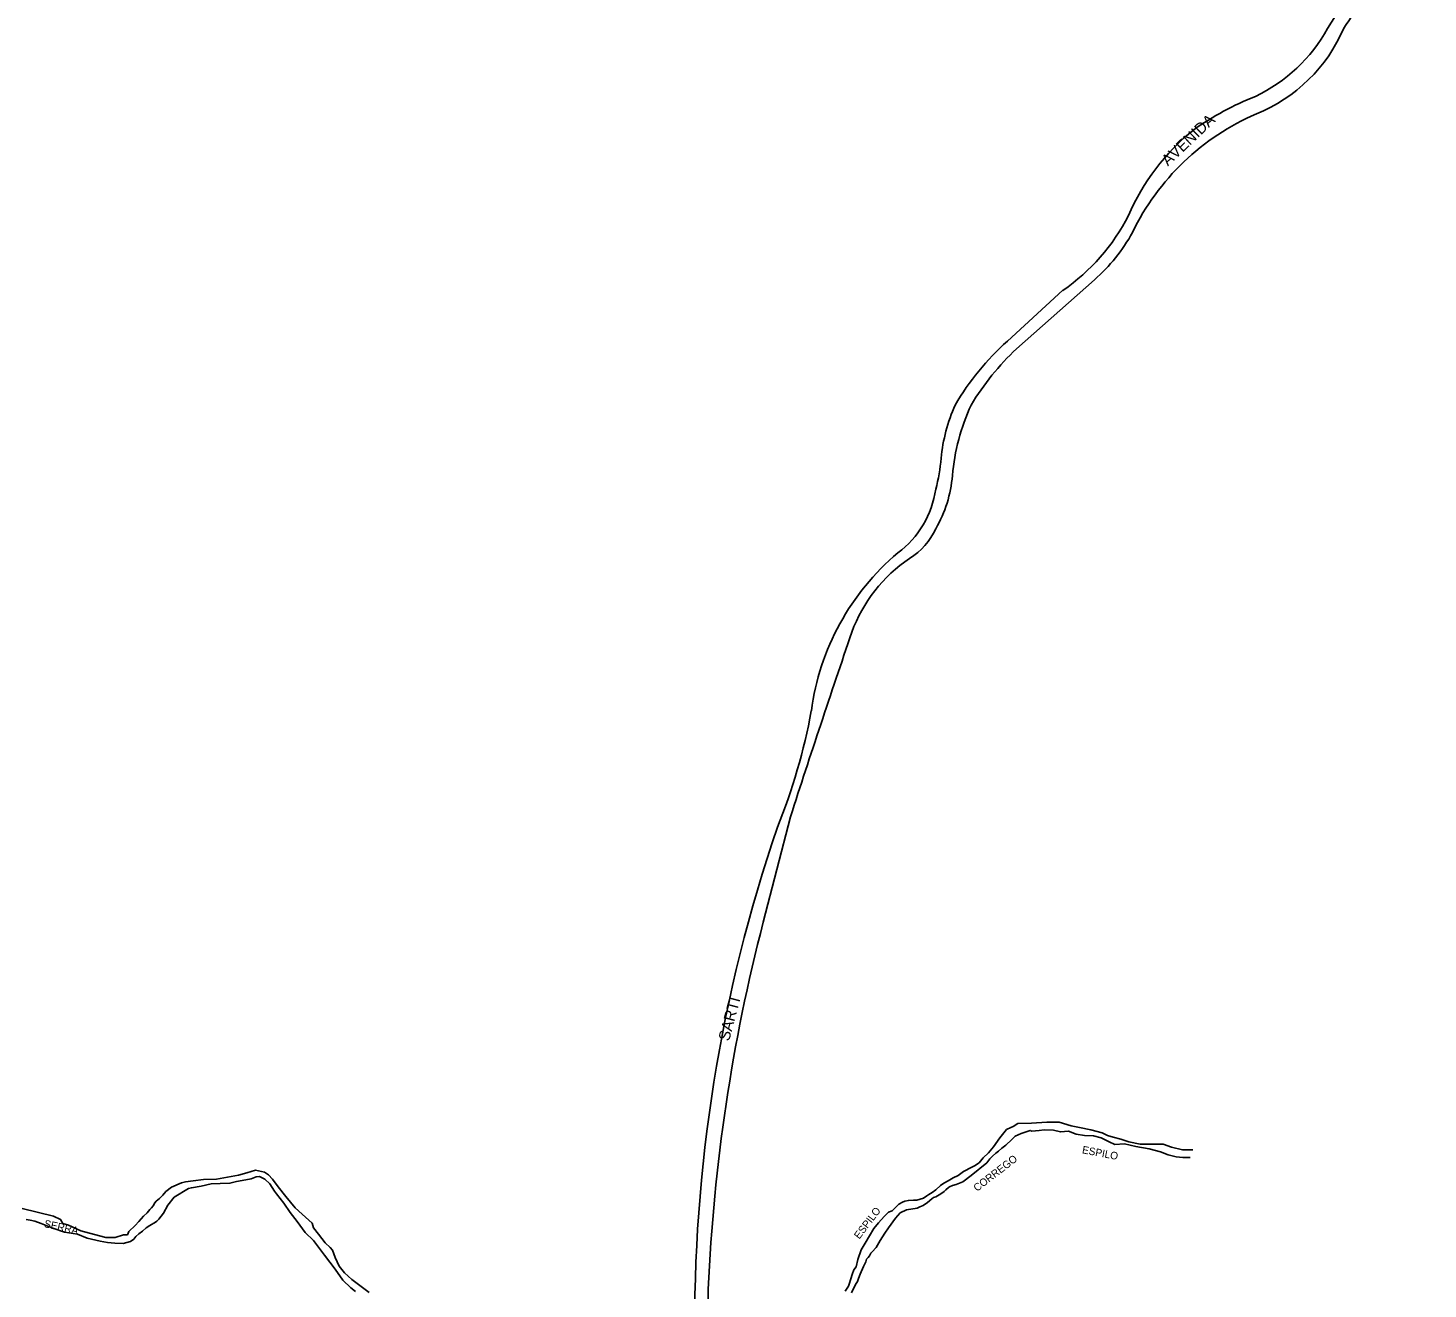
# Model space of a CAD drawing. Extents: x 325709 to 364434, y 7573432 to 7597073.
# Drawn here: x 344398 to 345143, y 7589031 to 7589703 of the extents above; entities that cross this region are included whole.
import ezdxf

# ---------------------------------------------------------------- set-up
doc = ezdxf.new("R2010")
doc.units = 0
for name, color, linetype in [('EDIFIDENTIF', 7, 'Continuous'), ('EDIFOBRAEXIS', 7, 'Continuous'), ('LOGRADOURO', 7, 'Continuous'), ('LOGRADOURO_TEXTO', 7, 'Continuous')]:
    doc.layers.add(name, color=color, linetype=linetype)

msp = doc.modelspace()

# ---------------------------------------------------------------- linework, layer by layer
at = {"layer": 'EDIFOBRAEXIS'}
for points in [[(344881.39, 7589084.09), (344883.94, 7589086.39), (344885.69, 7589087.77), (344888.03, 7589088.91), (344890.73, 7589090.47), (344893.33, 7589091.83), (344896.23, 7589093.83), (344900.67, 7589096.23), (344901.97, 7589097.01), (344904.54, 7589098.6), (344906.63, 7589101.19), (344909.46, 7589103.8), (344912.1, 7589106.96), (344915.5, 7589111.91), (344919.04, 7589116.19), (344921.29, 7589117.4), (344922.66, 7589117.88), (344925.18, 7589119.37), (344932.38, 7589119.6), (344940.59, 7589120.12), (344947.05, 7589120.15), (344953.5, 7589118.22), (344957.99, 7589117.31), (344963.94, 7589116.17), (344970.03, 7589114.45), (344972.75, 7589113.11), (344975.79, 7589112.26), (344979.83, 7589111.03), (344984.25, 7589109.61), (344990.27, 7589108.42), (345002.47, 7589108.42), (345006.96, 7589106.81), (345012.75, 7589105.44), (345018.22, 7589105.39)], [(344881.39, 7589080.43), (344883.25, 7589081.53), (344885.11, 7589082.69), (344885.87, 7589083.27), (344886.77, 7589084.14), (344888.12, 7589085.4), (344888.78, 7589085.8), (344890.38, 7589086.46), (344892.34, 7589086.98), (344895.88, 7589088.34), (344900.24, 7589091.73), (344908.58, 7589098.59), (344910.24, 7589100.59), (344911.69, 7589101.98), (344913.48, 7589103.6), (344914.86, 7589104.79), (344916.54, 7589106.31), (344918.71, 7589107.96), (344921.9, 7589110.94), (344923.63, 7589112.66), (344926.87, 7589114.05), (344931.73, 7589115.76), (344932.62, 7589115.33), (344936.53, 7589115.79), (344939.15, 7589116.04), (344944.13, 7589115.89), (344947.77, 7589114.99), (344952.14, 7589115.38), (344956.12, 7589113.74), (344960.62, 7589113.08), (344965.37, 7589112.81), (344969.46, 7589111.8), (344973.65, 7589109.73), (344976.8, 7589108.22), (344981.86, 7589108.65), (344987.95, 7589107.13), (344994.94, 7589106.01), (345001.08, 7589104.29), (345005.04, 7589102.77), (345009.28, 7589101.76), (345012.92, 7589101.34), (345016.78, 7589101.33)], [(344395.31, 7589074.17), (344412, 7589070.07), (344415.71, 7589068.3), (344416.83, 7589066.25), (344419.88, 7589065.3), (344426.41, 7589062.35), (344433.75, 7589060.45), (344439.85, 7589058.72), (344444.7, 7589058.86), (344449.19, 7589060.22), (344451.24, 7589060.23), (344452.02, 7589062.03), (344455.36, 7589065.14), (344457.26, 7589067.36), (344459.84, 7589070.13), (344461.73, 7589071.94), (344463.12, 7589073.75), (344464.01, 7589074.56), (344465.05, 7589075.56), (344465.9, 7589077.26), (344466.64, 7589078.18), (344468.26, 7589079.55), (344470.1, 7589081.23), (344471.77, 7589083.27), (344474.68, 7589085.62), (344480.11, 7589087.92), (344482.11, 7589088.33), (344486.24, 7589088.98), (344491.8, 7589089.71), (344498.63, 7589089.84), (344510.32, 7589092.03), (344514.73, 7589093.19), (344519.37, 7589094.53), (344524.27, 7589093.55), (344526.26, 7589092.12), (344528.55, 7589089.84), (344531.56, 7589085.81), (344535.51, 7589080.62), (344540.51, 7589074.65), (344544.2, 7589071.24), (344549.57, 7589066.36), (344550.29, 7589063.87), (344552.94, 7589060.56), (344556.46, 7589055.93), (344559.21, 7589053.52), (344560.38, 7589052.11), (344561.77, 7589048.18), (344563.99, 7589043.54), (344566.84, 7589040.05), (344570.61, 7589036.43), (344579.95, 7589029.56)], [(344397.36, 7589068.34), (344399.44, 7589067.97), (344402.08, 7589067.44), (344405.41, 7589066.16), (344411.56, 7589063.8), (344417.74, 7589061.64), (344424.74, 7589060.54), (344429.93, 7589058.48), (344436.79, 7589056.75), (344440.7, 7589056.16), (344444.56, 7589055.69), (344449.05, 7589055.55), (344452.93, 7589056.68), (344454.65, 7589057.8), (344455.81, 7589059.33), (344457.33, 7589060.71), (344459.28, 7589062.16), (344461.26, 7589063.84), (344463.28, 7589065.22), (344466.17, 7589066.96), (344466.95, 7589067.49), (344467.96, 7589068.49), (344470.42, 7589071.69), (344472.74, 7589075.91), (344476.1, 7589080.19), (344483.77, 7589084.94), (344485.37, 7589085.25), (344490.59, 7589086.15), (344495.77, 7589087.26), (344500.66, 7589087.43), (344505.84, 7589087.68), (344509.39, 7589088.63), (344514.26, 7589089.41), (344517.13, 7589090), (344519.87, 7589091), (344521.57, 7589091.16), (344524.41, 7589089.82), (344527.04, 7589087.37), (344529.49, 7589083.5), (344530.63, 7589082.08), (344534.58, 7589077.07), (344537.8, 7589072.08), (344541.52, 7589067.32), (344545.81, 7589061.45), (344550.24, 7589057.1), (344556.1, 7589049.4), (344561.79, 7589041.83), (344565.89, 7589036.04), (344570.17, 7589031.96), (344572.72, 7589030.07)], [(344833.2, 7589030.17), (344834.96, 7589032.89), (344835.37, 7589033.85), (344836.29, 7589036.85), (344837.02, 7589039.01), (344837.9, 7589041.58), (344838.99, 7589043.18), (344839.97, 7589046.99), (344841.72, 7589052.23), (344843.89, 7589055.79), (344848.49, 7589063.49), (344851.04, 7589066.52), (344853.92, 7589069.93), (344856.32, 7589072.2), (344858.15, 7589073.04), (344860.45, 7589075.24), (344861.77, 7589076.43), (344863.79, 7589077.58), (344864.93, 7589078.04), (344866.89, 7589078.53), (344869.65, 7589078.57), (344871.4, 7589078.7), (344874.92, 7589079.79), (344876.62, 7589081), (344877.77, 7589081.66), (344878.71, 7589082.2), (344879.46, 7589082.64), (344881.39, 7589084.09)], [(344836.5, 7589029.39), (344838.64, 7589033.81), (344839.78, 7589035.39), (344840.3, 7589036.89), (344841.26, 7589039.26), (344842.97, 7589043.37), (344844.16, 7589045.86), (344844.63, 7589047.16), (344845.11, 7589047.72), (344845.42, 7589048.18), (344846.13, 7589049.07), (344846.83, 7589050.39), (344847.64, 7589051.13), (344849.64, 7589053.4), (344851.88, 7589057.11), (344854.38, 7589061.15), (344856.2, 7589063.83), (344860.04, 7589069.14), (344862.57, 7589071.84), (344865.91, 7589073.55), (344871.47, 7589074.46), (344872.96, 7589075.08), (344874.64, 7589075.74), (344877.08, 7589077.33), (344879.37, 7589079.41), (344880.28, 7589080.08), (344881.39, 7589080.43)]]:
    msp.add_lwpolyline(points, dxfattribs=at)
at = {"layer": 'LOGRADOURO'}
for p, q in [((345143.37, 7589787.75), (345089.92, 7589702.39)), ((344924.43, 7589531.89), (344965.82, 7589568.59)), ((344949.09, 7589562.96), (344919.54, 7589535.92)), ((344804.11, 7589282.74), (344789.63, 7589226.67)), ((344760.38, 7589031.35), (344760.65, 7589001.91))]:
    msp.add_line(p, q, dxfattribs=at)
for centre, radius, start, end in [((344229.33, 7590298.49), 1053.89, 325.5686, 327.58287), ((345014.75, 7589743.75), 85.8, 295.3561, 331.17884), ((345020.22, 7589735.87), 85.13, 291.94327, 336.99442), ((345113.22, 7589513.24), 164.96, 111.97324, 124.96621), ((345103.84, 7589536.79), 130.82, 113.32857, 154.15867), ((345093.11, 7589555.83), 118.8, 128.79513, 156.75025), ((344887.5, 7589652.12), 108.37, 304.63277, 332.88411), ((344906.55, 7589637), 90.52, 310.909, 331.50488), ((345015.81, 7589428.75), 144.06, 131.93466, 149.47886), ((345023.12, 7589427.56), 143.61, 133.40861, 148.82092), ((344977.71, 7589464.13), 93.94, 156.28134, 174.22394), ((345003.94, 7589454.28), 114.1, 155.32817, 174.93048), ((344792.5, 7589480.98), 92.05, 344.94911, 355.39069), ((344823.53, 7589469.8), 66.98, 329.76035, 355.34767), ((344830.53, 7589464.37), 51.38, 306.76661, 351.8343), ((344848.08, 7589451.33), 36.65, 302.0319, 335.38524), ((344946.7, 7589321.74), 132.63, 130.08854, 172.46273), ((344912.97, 7589352.97), 81.21, 124.04295, 159.84557), ((350849.45, 7587328.84), 6353.26, 161.155398, 162.088713), ((344503.21, 7589396.46), 317.22, 337.90053, 349.59047), ((345572.94, 7589012.08), 819.83, 161.13862, 180.71027), ((345696.22, 7588991.03), 936.7, 165.43037, 177.5328)]:
    msp.add_arc(centre, radius, start, end, dxfattribs=at)

# ---------------------------------------------------------------- texts
at = {"layer": 'EDIFIDENTIF'}
for s, rotation, p in [('CORREGO', 37.71175, (344903.39, 7589083.01)), ('ESPILO', 349.17958, (344959.05, 7589103.66)), ('ESPILO', 52.84421, (344840.74, 7589057.62)), ('SERRA', 347.42867, (344406.68, 7589064.34))]:
    msp.add_text(s, height=4, rotation=rotation, dxfattribs=at).set_placement(p)
at = {"layer": 'LOGRADOURO_TEXTO'}
for s, rotation, p in [('AVENIDA', 43.32518, (345004.95, 7589628.84)), ('SARTI', 75.11343, (344771.44, 7589163))]:
    msp.add_text(s, height=6, rotation=rotation, dxfattribs=at).set_placement(p)

doc.saveas('drawing.dxf')
